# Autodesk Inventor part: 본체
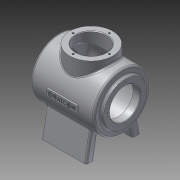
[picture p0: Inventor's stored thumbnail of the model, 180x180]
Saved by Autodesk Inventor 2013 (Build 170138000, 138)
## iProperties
Created: 2015-01
Part Number: 본체
Material: 알루미늄 6061
Document SubType Name: Modeling
Designer: Administrator
Density: 2.71 g/cm^3
Mass: 1021.13 g
Surface Area: 1060.37 cm^2
Volume: 376.8 cm^3
Author: Administrator
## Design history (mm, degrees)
sketch "스케치1"
  geometry: C1 r 50 at (0, 0); 1 further point
  constraints: 1 centre point, 1 coincident
  dimensions: "d0" = 100 diameter of C1
extrude "돌출1" new body sketch "스케치1" stored distance "d1" = 112; taper "d2" = 0 deg
node "작업 평면1"
node "작업 평면3"
sketch "스케치6"
  geometry: L1 (-48, -80)-(-34, -80); L2 (34, -80)-(48, -80); L3 (34, -80)-(27.282, -41.901); L4 (-48, -80)-(-39.336, -30.865); L5 (-34, -80)-(-27.282, -41.901); L6 (48, -80)-(39.336, -30.865); A1 r 50 centre (0, 0) between (27.282, -41.901) and (-39.336, -30.865) reference; 1 further point
  constraints: 12 end point, 4 point on circle, 2 horizontal
  dimensions: "d18" = 80 distance from line of point (0, 0) L1; "d19" = 80 distance from line of L2 point (0, 0); "d20" = 14 distance of L1.start L1.end; "d21" = 14 distance of L2.start L2.end; "d22" = 48 horizontal distance of point (0, 0) L1.start; "d23" = 48 horizontal distance of L2.end point (0, 0); "d26" = 100 deg angle of L1 L4; "d27" = 80 deg angle of L1 L5; "d28" = 80 deg angle of L2 L3; "d29" = 100 deg angle of L2 L6
extrude "돌출6" join sketch "스케치6" stored distance "d30" = 80; taper "d31" = 0 deg
sketch "스케치10"
  geometry: C1 r 50 at (0, 0) reference; C2 r 38 at (0, 0)
  constraints: 1 centre point, 1 coincident
  dimensions: "d43" = 76 diameter of C2
extrude "돌출9" join sketch "스케치10" distance "d44" = 5; taper "d45" = 0 deg
sketch "스케치11"
  geometry: C1 r 38 at (0, 0) reference; C2 r 27 at (0, 0)
  constraints: 1 centre point, 1 coincident
  dimensions: "d46" = 54 diameter of C2
extrude "돌출10" cut sketch "스케치11" distance "d47" = 13; taper "d48" = 0 deg
sketch "스케치12"
  geometry: C1 r 38 at (0, 0) reference; C2 r 27 at (0, 0)
  constraints: 1 centre point, 1 coincident
  dimensions: "d49" = 54 diameter of C2
extrude "돌출11" cut sketch "스케치12" distance "d50" = 12; taper "d51" = 0 deg
node "작업 평면5"
sketch "스케치13"
  geometry: C1 r 45 at (0, 0); 1 further point
  constraints: 1 centre point, 1 coincident
  dimensions: "d53" = 90 diameter of C1
extrude "돌출12" cut sketch "스케치13" distance "d54" = 97; taper "d55" = 0 deg
sketch "스케치16"
  geometry: C1 r 27 at (0, 0) reference; 1 further point
  constraints: 1 vertical alignment
  dimensions: "d62" = 32 distance of C1.centre point (0, 32)
hole "구멍1" sketch "스케치16" at (0, 32) diameter "d63" = 3.242; stored, may be unused: countersink angle "d67" = 90 deg, drill point angle "d69" = 118 deg; dims "d64" = 8, "d65" = 4, "d66" = 2, "d68" = 10
fillet "모깎기1" dims "d84" = 3
fillet "모깎기2" dims "d85" = 3
chamfer "모따기1" distance "d87" = 1; stored, may be unused: second distance "d88" = 2, angle "d89" = 45 deg
node "작업 평면7"
sketch "스케치18"
  geometry: L1 (-61, -38)-(-61, 38) reference; L2 (-26, 6)-(28, 6); L3 (28, 6)-(28, -6); L4 (28, -6)-(-26, -6); L5 (-26, -6)-(-26, 6); 1 further point
  constraints: 8 end point, 2 perpendicular, 1 horizontal, 1 midpoint, 1 parallel
  dimensions: "d123" = 54 distance of L2.start L2.end; "d125" = 12 distance of L4.end L2.start; "d126" = 35 distance between parallel lines of L1 L5; "d127" = 6 distance from line of point (-61, 0) L2
extrude "돌출15" join sketch "스케치18" stored distance "d93" = 97; taper "d94" = 0 deg
sketch "스케치20"
  geometry: L1 (-61, -38)-(-61, 38) reference; C1 r 38 at (1, 0); 1 further point
  constraints: 1 centre point, 1 horizontal alignment
  dimensions: "d97" = 76 diameter of C1; "d98" = 62 distance from line of L1 C1.centre
extrude "돌출16" join sketch "스케치20" stored distance "d99" = 97; taper "d100" = 0 deg
sketch "스케치21"
  geometry: C1 r 38 at (0, 0) reference; C2 r 27 at (0, 0); 1 further point
  constraints: 1 centre point, 1 coincident
  dimensions: "d101" = 54 diameter of C2
extrude "돌출17" cut sketch "스케치21" stored distance "d103" = 97; taper "d104" = 0 deg
sketch "스케치22"
  geometry: C1 r 27 at (0, 0) reference; 2 further points
  constraints: 1 vertical alignment
  dimensions: "d105" = 32 distance of C1.centre point (0, 32)
hole "구멍3" sketch "스케치22" at (0, 32) diameter "d106" = 3.242; stored, may be unused: countersink angle "d110" = 90 deg, drill point angle "d112" = 118 deg; dims "d107" = 8, "d108" = 4, "d109" = 2, "d111" = 10
fillet "모깎기4" dims "d116" = 3
chamfer "모따기2" distance "d117" = 1; stored, may be unused: second distance "d118" = 2, angle "d119" = 45 deg
sketch "스케치23"
  geometry: L1 (28, -6)-(-26, -6) reference; L2 (28, 6)-(28, -6) reference; 2 further points
  constraints: 1 other
  dimensions: "d128" = 6 distance from line of L1 point (1, 0); "d129" = 27 distance from line of L2 point (1, 0)
feature "엠보싱3" sketch "스케치23" dims "d2" = 0, "d130" = 0.5, "d131" = 0
node "솔리드1"
mirror "대칭2"
pattern_circular "원형 패턴1" dims angle "d71" = 360 deg
mirror "대칭3"
pattern_circular "원형 패턴3" dims angle "d114" = 360 deg
other parameters: "d6" = -12, "d10" = 62, "d52" = -13, "d90" = -52
